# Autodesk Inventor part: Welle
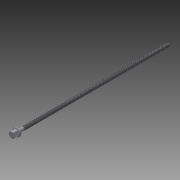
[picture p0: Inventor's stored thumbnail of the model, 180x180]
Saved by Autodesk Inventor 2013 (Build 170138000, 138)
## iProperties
Created: 2012-11
Part Number: Welle
Material: Allgemein
Document SubType Name: Modeling
Designer: s0536599
Density: 1 g/cm^3
Author: s0536599
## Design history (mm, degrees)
sketch "Skizze1"
  geometry: L1 (0, -16.8)-(0, 16.8) reference; L2 (19.399, 0)-(-19.399, 0) reference; L3 (-13.856, 0)-(-6.928, 12); L4 (-6.928, 12)-(6.928, 12); L5 (6.928, 12)-(13.856, 0); L6 (13.856, 0)-(6.928, -12); L7 (6.928, -12)-(-6.928, -12); L8 (-6.928, -12)-(-13.856, 0); C1 r 6 at (0, 0); 2 further points
  constraints: 12 end point, 2 coincident, 1 centre point, 1 point on line, 13 other
  dimensions: "d0" = 12 diameter of C1; "d1" = 24 distance of L3.end L7.end
extrude "Extrusion1" new body sketch "Skizze1" distance "d2" = 20; taper "d3" = 0 deg
sketch "Skizze2"
  geometry: C1 r 6 at (0, 0) reference; C2 r 17.5 at (0, 0)
  constraints: 1 centre point, 1 coincident
  dimensions: "d4" = 35 diameter of C2
extrude "Extrusion2" join sketch "Skizze2" distance "d7" = 5; taper "d8" = 0 deg
sketch "Skizze3"
  geometry: C1 r 8 at (0, 0); 1 further point
  constraints: 1 centre point, 1 coincident
  dimensions: "d17" = 16 diameter of C1
extrude "Extrusion3" join sketch "Skizze3" distance "d9" = 700; taper "d10" = 0 deg
fillet "Rundung1" dims "d13" = 2
feature "Gewinde2" dims "d18" = 650, "d19" = 0
node "Volumenkörper1"
